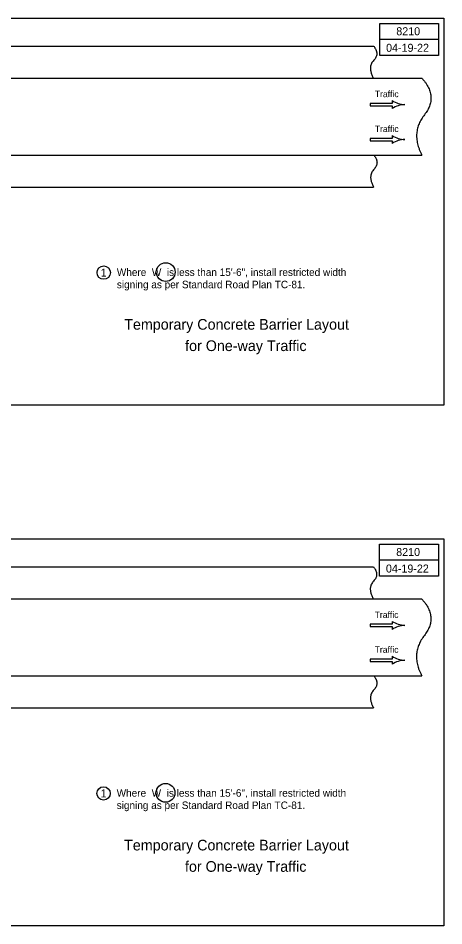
# Model space of a CAD drawing. Extents: x 10148 to 16528, y 8070 to 10905.
# Drawn here: x 12456 to 13253, y 9204 to 10905 of the extents above; entities that cross this region are included whole.
import ezdxf

# ---------------------------------------------------------------- set-up
doc = ezdxf.new("R2010")
doc.units = 0
for name, color, linetype in [('Sheet_Table Border', 7, 'Continuous'), ('SheetText', 7, 'Continuous'), ('TC_PCCPavement', 7, 'Continuous'), ('TC_ShoulderGranular', 7, 'Continuous')]:
    doc.layers.add(name, color=color, linetype=linetype)

msp = doc.modelspace()

# ---------------------------------------------------------------- linework, layer by layer
at = {"layer": 'Sheet_Table Border'}
for p, q in [((10148, 10904.5), (13253, 10904.5)), ((13253, 10904.5), (13253, 10179.5)), ((13253, 10179.5), (10148, 10179.5)), ((10147.7, 9928.8), (13252.7, 9928.8)), ((13252.7, 9928.8), (13252.7, 9203.8)), ((13252.7, 9203.8), (10147.7, 9203.8))]:
    msp.add_line(p, q, dxfattribs=at)
for points in [[(13243, 10894.5), (13243, 10834.5), (13133, 10834.5), (13133, 10894.5), (13243, 10894.5), (13243, 10864.5), (13133, 10864.5)], [(13242.7, 9918.8), (13242.7, 9858.8), (13132.7, 9858.8), (13132.7, 9918.8), (13242.7, 9918.8), (13242.7, 9888.8), (13132.7, 9888.8)]]:
    msp.add_lwpolyline(points, dxfattribs=at)
at = {"layer": 'SheetText'}
for p, q in [((13156.3, 10750), (13156.3, 10744.8)), ((13156.3, 10744.8), (13115, 10744.8)), ((13115, 10744.8), (13115, 10740.3)), ((13115, 10740.3), (13156.3, 10740.3)), ((13156.3, 10740.3), (13156.3, 10735)), ((13180.2, 10742.5), (13180.2, 10742.5)), ((13156.3, 10684.6), (13156.3, 10679.3)), ((13156.3, 10679.3), (13115, 10679.3)), ((13115, 10679.3), (13115, 10674.8)), ((13115, 10674.8), (13156.3, 10674.8)), ((13156.3, 10674.8), (13156.3, 10669.6)), ((13180.2, 10677.1), (13180.2, 10677.1)), ((13156.1, 9769.1), (13114.8, 9769.1)), ((13114.8, 9769.1), (13114.8, 9764.6)), ((13114.8, 9764.6), (13156.1, 9764.6)), ((13156.1, 9774.3), (13156.1, 9769.1)), ((13156.1, 9764.6), (13156.1, 9759.3)), ((13180, 9766.8), (13180, 9766.8)), ((13156.1, 9703.6), (13114.8, 9703.6)), ((13114.8, 9703.6), (13114.8, 9699.1)), ((13114.8, 9699.1), (13156.1, 9699.1)), ((13156.1, 9708.9), (13156.1, 9703.6)), ((13156.1, 9699.1), (13156.1, 9693.9)), ((13180, 9701.4), (13180, 9701.4))]:
    msp.add_line(p, q, dxfattribs=at)
for centre, radius in [((12732.4, 10428.8), 17.6), ((12616.3, 10427.7), 12.5), ((12616, 9452), 12.5), ((12732.1, 9453.1), 17.6)]:
    msp.add_circle(centre, radius, dxfattribs=at)
for centre, start, end in [((13182.2, 10790.9), 237.618, 267.648), ((13182.2, 10694.2), 92.352, 122.382), ((13182.2, 10725.4), 237.618, 267.648), ((13182.2, 10628.8), 92.352, 122.382), ((13182, 9815.2), 237.618, 267.648), ((13182, 9718.5), 92.352, 122.382), ((13182, 9749.7), 237.618, 267.648), ((13182, 9653.1), 92.352, 122.382)]:
    msp.add_arc(centre, 48.4, start, end, dxfattribs=at)
at = {"layer": 'TC_PCCPavement'}
for p, q in [((11880.6, 10792), (13211.9, 10792)), ((11743.2, 10648), (13211.9, 10648)), ((11880.4, 9816.3), (13211.7, 9816.3)), ((11742.9, 9672.3), (13211.7, 9672.3))]:
    msp.add_line(p, q, dxfattribs=at)
for points in [[(13211.9, 10792), (13243.4, 10757.5), (13190, 10689.5), (13211.9, 10648)], [(13211.7, 9816.3), (13243.1, 9781.8), (13189.8, 9713.8), (13211.7, 9672.3)]]:
    msp.add_open_spline(points, degree=2, dxfattribs=at)
at = {"layer": 'TC_ShoulderGranular'}
for p, q in [((11773.2, 10852), (13121.6, 10852)), ((11773.2, 10588), (13121.6, 10588)), ((11772.9, 9876.3), (13121.3, 9876.3)), ((11772.9, 9612.3), (13121.3, 9612.3))]:
    msp.add_line(p, q, dxfattribs=at)
for points in [[(13121.6, 10852), (13133.4, 10837.8), (13109.8, 10812.8), (13121.1, 10792)], [(13122, 10647.9), (13133.8, 10633.8), (13110.2, 10608.8), (13121.6, 10588)], [(13121.3, 9876.3), (13133.1, 9862.1), (13109.5, 9837.1), (13120.9, 9816.3)], [(13121.8, 9672.2), (13133.6, 9658.1), (13110, 9633.1), (13121.3, 9612.3)]]:
    msp.add_open_spline(points, degree=2, dxfattribs=at)

# ---------------------------------------------------------------- texts
at = {"layer": 'SheetText'}
for s, height, p in [('8210', 15, (13164, 10872.5)), ('04-19-22', 15, (13144.9, 10841.5)), ('Traffic', 12, (13123.8, 10756.5)), ('Traffic', 12, (13123.8, 10691.1)), ('1', 15, (12610.7, 10420.2)), ('Where  W  is less than 15\'-6", install restricted width', 14, (12640.9, 10421.5)), ('signing as per Standard Road Plan TC-81.', 14, (12640.9, 10398.5)), ('Temporary Concrete Barrier Layout', 20, (12654.7, 10320.8)), ('for One-way Traffic', 20, (12768.7, 10280.8)), ('8210', 15, (13163.8, 9896.8)), ('04-19-22', 15, (13144.6, 9865.8)), ('Traffic', 12, (13123.5, 9780.8)), ('Traffic', 12, (13123.5, 9715.4)), ('1', 15, (12610.4, 9444.5)), ('Where  W  is less than 15\'-6", install restricted width', 14, (12640.6, 9445.8)), ('signing as per Standard Road Plan TC-81.', 14, (12640.6, 9422.8)), ('Temporary Concrete Barrier Layout', 20, (12654.5, 9345.1)), ('for One-way Traffic', 20, (12768.4, 9305.1))]:
    msp.add_text(s, height=height, dxfattribs=at).set_placement(p)

doc.saveas('drawing.dxf')
